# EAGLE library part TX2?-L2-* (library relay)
TX Relay 2 coil latching NAiS 2 AMP. HIGH CAPACITY RELAY WITH HIGH SURGE VOLTAGE & HIGH BREAKDOWN VOLTAGE Source: http://www.mew-europe.com/.. en_ds_61022_0001.pdf TX-S SMALL POLARIZED WITH HIGH SENSITIVITY 50mW Source: http://www.mew-europe.com/.. en_ds_61022_0022.pdf
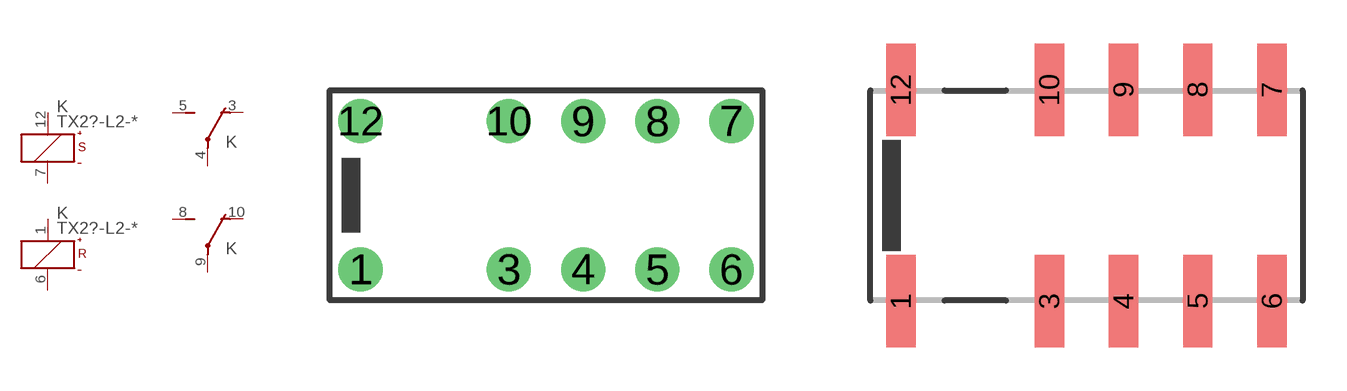
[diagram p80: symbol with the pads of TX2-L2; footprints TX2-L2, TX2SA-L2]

Designator prefix K; gates S=K+-S R=K+-R 1=U 2=U

## TX2-L2-1.5V (OC_FARNELL: unknown; OC_NEWARK: unknown), TX2-L2-3V (MPN: TX2-L2-3V-1; OC_FARNELL: unknown; OC_NEWARK: 12N3980), TX2-L2-4.5V (MPN: TX2-L2-4.5V; OC_FARNELL: unknown; OC_NEWARK: 15P9981), TX2-L2-5V (MPN: TX2-L2-5V; OC_FARNELL: 625826; OC_NEWARK: 15P9982), TX2-L2-6V (OC_FARNELL: unknown; OC_NEWARK: unknown), TX2-L2-9V (MPN: TX2-L2-9V; OC_FARNELL: unknown; OC_NEWARK: 15P9984), TX2-L2-12V (MF: AROMAT/ MATSUSHITA; MPN: TX2-L2-12V; OC_FARNELL: 1124060; OC_NEWARK: 64K3213), TX2-L2-24V (MPN: TX2-L2-24V; OC_FARNELL: 1124061; OC_NEWARK: 31M0467)  [TX2-L2]
1  R:+  pas
3  1:O  pas
4  1:P  pas
5  1:S  pas
6  R:-  pas
7  S:-  pas
8  2:S  pas
9  2:P  pas
10  2:O  pas
12  S:+  pas

## TX2SA-L2-1.5V (OC_FARNELL: unknown; OC_NEWARK: unknown), TX2SA-L2-3V (MPN: TX2SA-L2-3V; OC_FARNELL: unknown; OC_NEWARK: 15P9991), TX2SA-L2-4.5V (MPN: TX2SA-L2-4.5V; OC_FARNELL: unknown; OC_NEWARK: 15P9993), TX2SA-L2-5V (MPN: TX2SA-L2-5V; OC_FARNELL: unknown; OC_NEWARK: 15P9995), TX2SA-L2-6V (MPN: TX2SA-L2-6V-X; OC_FARNELL: unknown; OC_NEWARK: 13P9578), TX2SA-L2-9V (OC_FARNELL: unknown; OC_NEWARK: unknown), TX2SA-L2-12V (MF: AROMAT/ MATSUSHITA; MPN: TX2SA-L2-12V; OC_FARNELL: unknown; OC_NEWARK: 92F1610), TX2SA-L2-24V (MPN: TX2SA-L2-24V-1; OC_FARNELL: unknown; OC_NEWARK: 12N3986)  [TX2SA-L2]
Pads as for TX2-L2

## TX2SL-L2-1.5V (OC_FARNELL: unknown; OC_NEWARK: unknown), TX2SL-L2-3V (OC_FARNELL: unknown; OC_NEWARK: unknown), TX2SL-L2-4.5V (MPN: TX2SL-L2-4.5V; OC_FARNELL: unknown; OC_NEWARK: 15P9998), TX2SL-L2-5V (MPN: TX2SL-L2-5V; OC_FARNELL: unknown; OC_NEWARK: 16P0001), TX2SL-L2-6V (OC_FARNELL: unknown; OC_NEWARK: unknown), TX2SL-L2-9V (MPN: TX2SL-L2-9V-Z; OC_FARNELL: unknown; OC_NEWARK: 16P0002), TX2SL-L2-12V (OC_FARNELL: unknown; OC_NEWARK: unknown), TX2SL-L2-24V (OC_FARNELL: unknown; OC_NEWARK: unknown)  [TX2SL-L2]
Pads as for TX2-L2

## TX2SS-L2-1.5V (OC_FARNELL: unknown; OC_NEWARK: unknown), TX2SS-L2-3V (OC_FARNELL: unknown; OC_NEWARK: unknown), TX2SS-L2-4.5V (OC_FARNELL: unknown; OC_NEWARK: unknown), TX2SS-L2-5V (OC_FARNELL: unknown; OC_NEWARK: unknown), TX2SS-L2-6V (OC_FARNELL: unknown; OC_NEWARK: unknown), TX2SS-L2-9V (MPN: TX2SS-L2-9V; OC_FARNELL: unknown; OC_NEWARK: 16P0003), TX2SS-L2-12V (OC_FARNELL: unknown; OC_NEWARK: unknown), TX2SS-L2-24V (OC_FARNELL: unknown; OC_NEWARK: unknown)  [TX2SS-L2]
Pads as for TX2-L2

## TX2S2SA-L2-1.5V (OC_FARNELL: unknown; OC_NEWARK: unknown), TX2S2SA-L2-3V (OC_FARNELL: unknown; OC_NEWARK: unknown), TX2S2SA-L2-4.5V (OC_FARNELL: unknown; OC_NEWARK: unknown), TX2S2SA-L2-5V (OC_FARNELL: unknown; OC_NEWARK: unknown), TX2S2SA-L2-6V (OC_FARNELL: unknown; OC_NEWARK: unknown), TX2S2SA-L2-9V (OC_FARNELL: unknown; OC_NEWARK: unknown), TX2S2SA-L2-12V (OC_FARNELL: unknown; OC_NEWARK: unknown), TX2S2SA-L2-24V (OC_FARNELL: unknown; OC_NEWARK: unknown)  [TX2SA-L2]
Pads as for TX2-L2

## TX2S2SL-L2- (OC_FARNELL: unknown; OC_NEWARK: unknown)  [TX2SL-L2]
Pads as for TX2-L2

## TX2S2SS-L2- (OC_FARNELL: unknown; OC_NEWARK: unknown)  [TX2SS-L2]
Pads as for TX2-L2

## Footprint TX2-L2 (pad centres in mm)
2 AMP. HIGH CAPACITY RELAY NAiS WITH HIGH SURGE VOLTAGE & HIGH BREAKDOWN VOLTAGE 2 coil latching Source: http://www.mew-europe.com/.. en_ds_61022_0001.pdf
drill 1 round: 1 -6.35,-2.54; 3 -1.27,-2.54; 4 1.27,-2.54; 5 3.81,-2.54; 6 6.35,-2.54; 7 6.35,2.54; 8 3.81,2.54; 9 1.27,2.54; 10 -1.27,2.54; 12 -6.35,2.54

## Footprint TX2SA-L2 (pad centres in mm)
2 AMP. HIGH CAPACITY RELAY NAiS WITH HIGH SURGE VOLTAGE & HIGH BREAKDOWN VOLTAGE 2 coil latching Source: http://www.mew-europe.com/.. en_ds_61022_0001.pdf
smd 1 x 3.16: 1 -6.35,-3.62; 3 -1.27,-3.62; 4 1.27,-3.62; 5 3.81,-3.62; 6 6.35,-3.62; 7 6.35,3.62; 8 3.81,3.62; 9 1.27,3.62; 10 -1.27,3.62; 12 -6.35,3.62

## Footprint TX2SL-L2 (pad centres in mm)
2 AMP. HIGH CAPACITY RELAY NAiS WITH HIGH SURGE VOLTAGE & HIGH BREAKDOWN VOLTAGE 2 coil latching Source: http://www.mew-europe.com/.. en_ds_61022_0001.pdf
smd 1 x 3.16: 1 -6.35,-3.62; 3 -1.27,-3.62; 4 1.27,-3.62; 5 3.81,-3.62; 6 6.35,-3.62; 7 6.35,3.62; 8 3.81,3.62; 9 1.27,3.62; 10 -1.27,3.62; 12 -6.35,3.62

## Footprint TX2SS-L2 (pad centres in mm)
2 AMP. HIGH CAPACITY RELAY NAiS WITH HIGH SURGE VOLTAGE & HIGH BREAKDOWN VOLTAGE 2 coil latching Source: http://www.mew-europe.com/.. en_ds_61022_0001.pdf
smd 1 x 2.16: 1 -6.35,-3.12; 3 -1.27,-3.12; 4 1.27,-3.12; 5 3.81,-3.12; 6 6.35,-3.12; 7 6.35,3.12; 8 3.81,3.12; 9 1.27,3.12; 10 -1.27,3.12; 12 -6.35,3.12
